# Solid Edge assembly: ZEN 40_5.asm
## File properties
Title: Zylinder
Author: ahadarics
Template: iso metric assembly.asm
Last saved by: ahadarics
Revision: 8
Application: Solid Edge
Username: ahadarics
Dokumentum tartalom típus: 1
Document Number: ZEN 40/5
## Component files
Kit_2.par
Kolbenstange.par
Kit_1.par
Profilrohr.par
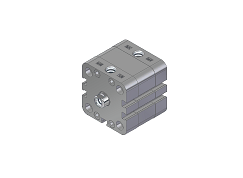
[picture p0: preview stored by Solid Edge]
